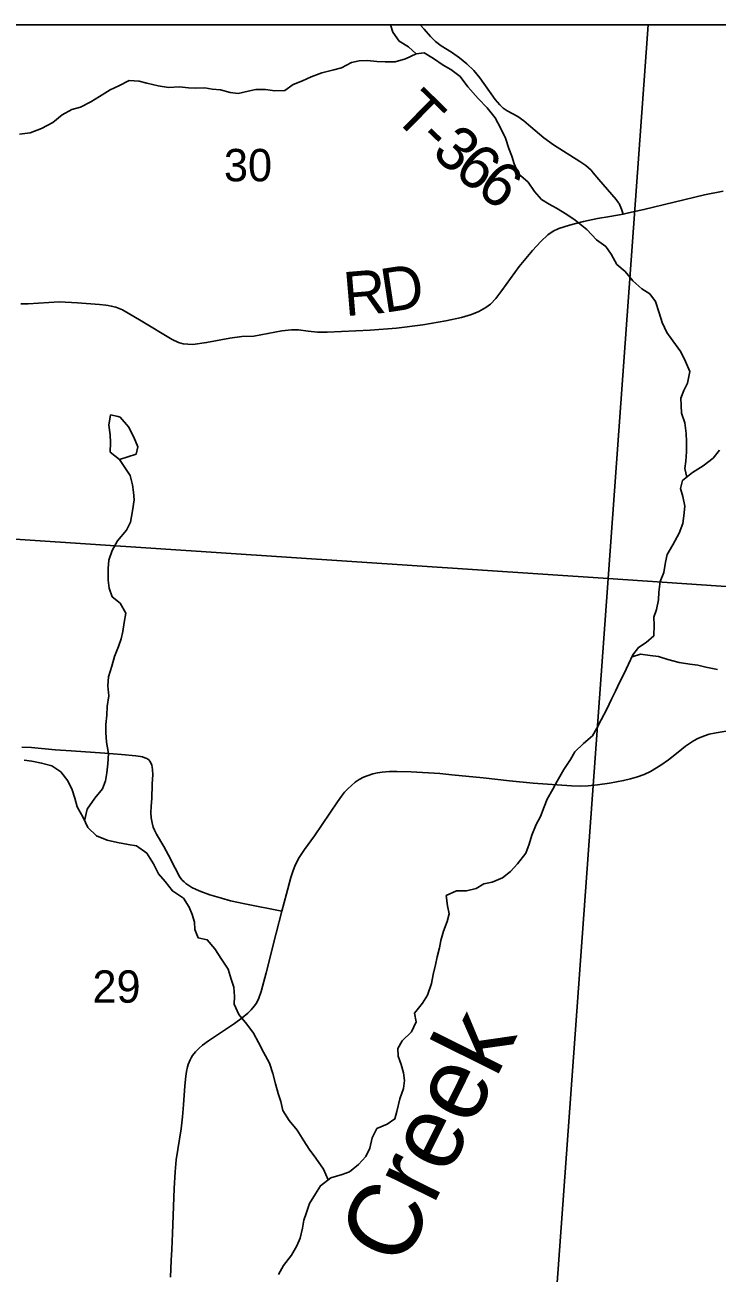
# Model space of a CAD drawing. Extents: x 39.8 to 73.8, y 13 to 35.
# Drawn here: x 44.827 to 45.722, y 32.252 to 33.865 of the extents above; entities that cross this region are included whole.
import ezdxf

# ---------------------------------------------------------------- set-up
doc = ezdxf.new("R2010")
doc.units = 0
for name, color, linetype in [('GM_X_Corporation', 7, 'Continuous'), ('GM_X_County_Road', 7, 'Continuous'), ('GM_X_Minor_Lake', 7, 'Continuous'), ('GM_X_Minor_River', 7, 'Continuous'), ('GM_X_Minor_River_Text', 7, 'Continuous'), ('GM_X_Section_Text', 7, 'Continuous'), ('GM_X_Township_Road', 7, 'Continuous'), ('GM_X_Township_Road_Text', 7, 'Continuous'), ('SH_Data', 7, 'Continuous')]:
    doc.layers.add(name, color=color, linetype=linetype)

msp = doc.modelspace()

# ---------------------------------------------------------------- linework, layer by layer
at = {"layer": 'GM_X_Corporation'}
msp.add_lwpolyline([(48.663, 33.865), (43.6158, 33.865), (43.5817, 33.4098), (43.5681, 33.1854), (43.5465, 32.861), (43.546, 32.8532), (43.5449, 32.8368), (43.542, 32.7932), (43.5417, 32.788), (43.5004, 32.1696), (43.4879, 31.9992), (43.4604, 31.6234), (43.4594, 31.6102), (43.4278, 31.1804), (43.4119, 30.9413), (43.3611, 30.1764), (43.3611, 30.1536), (43.3561, 30.0855), (43.3525, 30.036), (43.3481, 29.9766)], dxfattribs=at)
for points in [[(45.6327, 33.865), (44.6253, 33.865), (44.5795, 33.2157), (45.5809, 33.1493)], [(46.6307, 33.865), (45.6327, 33.865), (45.5809, 33.1493), (46.5718, 33.0824)], [(45.5809, 33.1493), (45.5069, 32.1262), (44.516, 32.1957), (44.5795, 33.2157)], [(45.5809, 33.1493), (46.5718, 33.0824), (46.4973, 32.0662), (45.5069, 32.1262)]]:
    msp.add_lwpolyline(points, close=True, dxfattribs=at)
at = {"layer": 'GM_X_County_Road'}
for points in [[(45.015, 32.2464), (45.016, 32.2681), (45.0165, 32.2821), (45.0174, 32.303), (45.0198, 32.3612), (45.021, 32.3828), (45.0224, 32.3983), (45.0287, 32.4382), (45.0305, 32.4535), (45.0318, 32.469), (45.0334, 32.4938), (45.0346, 32.5062), (45.0355, 32.5124), (45.0369, 32.5185), (45.0378, 32.5215), (45.039, 32.5245), (45.0403, 32.5274), (45.0418, 32.5301), (45.0435, 32.5328), (45.0474, 32.5378), (45.0518, 32.5423), (45.0565, 32.5464), (45.0641, 32.5519), (45.0796, 32.5623), (45.0978, 32.5742), (45.1078, 32.5815), (45.115, 32.5875), (45.1193, 32.5919), (45.1233, 32.5966), (45.125, 32.599), (45.1266, 32.6016), (45.1291, 32.6071), (45.132, 32.6159), (45.1386, 32.6398), (45.1517, 32.6909), (45.1591, 32.7196), (45.1649, 32.7419), (45.1705, 32.7631), (45.1735, 32.772), (45.1759, 32.7778), (45.1784, 32.7834), (45.1814, 32.789), (45.1884, 32.7993), (45.201, 32.817), (45.2307, 32.8607), (45.2362, 32.8683), (45.2401, 32.8732), (45.2443, 32.8778), (45.2489, 32.8821), (45.2538, 32.8861), (45.259, 32.8896), (45.2646, 32.8926), (45.2704, 32.895), (45.2764, 32.8969), (45.2825, 32.8983), (45.2887, 32.8993), (45.298, 32.9), (45.3074, 32.9001), (45.326, 32.8997), (45.3633, 32.8974), (45.3787, 32.8959), (45.4194, 32.8918), (45.4531, 32.888), (45.4837, 32.8851), (45.5333, 32.8816), (45.5456, 32.8812), (45.5549, 32.8815), (45.5672, 32.8827), (45.5825, 32.885), (45.6008, 32.8883), (45.6099, 32.8904), (45.6187, 32.893), (45.6274, 32.8962), (45.6358, 32.9001), (45.6489, 32.9081), (45.659, 32.9153), (45.6712, 32.925), (45.6809, 32.9327), (45.686, 32.9364), (45.6913, 32.9397), (45.6968, 32.9427), (45.6997, 32.944), (45.7055, 32.9463), (45.7115, 32.9481), (45.7207, 32.9501), (45.7361, 32.9525)], [(44.8227, 32.9317), (44.8351, 32.931), (44.8658, 32.9282), (44.8866, 32.9268), (44.9298, 32.9236), (44.9515, 32.9221), (44.97, 32.9205), (44.976, 32.9196), (44.9789, 32.9189), (44.9817, 32.9179), (44.9844, 32.9167), (44.9867, 32.915), (44.9881, 32.9133), (44.9895, 32.9111), (44.9906, 32.9083), (44.9912, 32.9055), (44.9916, 32.9022), (44.9919, 32.8962), (44.9914, 32.8838), (44.9906, 32.865), (44.9898, 32.8552), (44.9895, 32.8465), (44.99, 32.8402), (44.9911, 32.8339), (44.9927, 32.8283), (44.9943, 32.8243), (44.9968, 32.8192), (45.0063, 32.8031), (45.0124, 32.7919), (45.0208, 32.7752), (45.0265, 32.7643), (45.0282, 32.7618), (45.0301, 32.7596), (45.0324, 32.7574), (45.0348, 32.7553), (45.0374, 32.7535), (45.0427, 32.7502), (45.0483, 32.7474), (45.0541, 32.745), (45.0658, 32.7408), (45.0807, 32.7362), (45.0927, 32.7329), (45.1109, 32.7292), (45.1591, 32.7196)]]:
    msp.add_lwpolyline(points, dxfattribs=at)
at = {"layer": 'GM_X_Minor_Lake'}
for p, q in [((44.9372, 33.3611), (44.9353, 33.3478)), ((44.9471, 33.3587), (44.9372, 33.3611)), ((44.9353, 33.3478), (44.9369, 33.3353)), ((44.9497, 33.3581), (44.9471, 33.3587)), ((44.9607, 33.3456), (44.9497, 33.3581)), ((44.9676, 33.332), (44.9607, 33.3456)), ((44.9369, 33.3353), (44.9373, 33.3255)), ((44.9729, 33.3199), (44.9676, 33.332)), ((44.9373, 33.3255), (44.937, 33.3126)), ((44.937, 33.3126), (44.9488, 33.3035)), ((44.9707, 33.3104), (44.9729, 33.3199)), ((44.9488, 33.3035), (44.9707, 33.3104))]:
    msp.add_line(p, q, dxfattribs=at)
at = {"layer": 'GM_X_Minor_River'}
for p, q in [((45.3023, 33.8558), (45.2993, 33.865)), ((45.3107, 33.8441), (45.3023, 33.8558)), ((45.3225, 33.8365), (45.3107, 33.8441)), ((45.3328, 33.8278), (45.3225, 33.8365)), ((45.343, 33.829), (45.3328, 33.8278)), ((45.3551, 33.8215), (45.343, 33.829)), ((45.2491, 33.8166), (45.2359, 33.8097)), ((45.259, 33.8185), (45.2491, 33.8166)), ((45.2696, 33.8189), (45.259, 33.8185)), ((45.2817, 33.8178), (45.2696, 33.8189)), ((45.2923, 33.8175), (45.2817, 33.8178)), ((45.3055, 33.8175), (45.2923, 33.8175)), ((45.3188, 33.8213), (45.3055, 33.8175)), ((45.3328, 33.8278), (45.3188, 33.8213)), ((45.3677, 33.8128), (45.3551, 33.8215)), ((45.3775, 33.8075), (45.3677, 33.8128)), ((45.1969, 33.7978), (45.1856, 33.7928)), ((45.2106, 33.8032), (45.1969, 33.7978)), ((45.2261, 33.807), (45.2106, 33.8032)), ((45.2359, 33.8097), (45.2261, 33.807)), ((45.3897, 33.7984), (45.3775, 33.8075)), ((45.3996, 33.7848), (45.3897, 33.7984)), ((44.9369, 33.7811), (44.9233, 33.7723)), ((44.9482, 33.7864), (44.9369, 33.7811)), ((44.9614, 33.7933), (44.9482, 33.7864)), ((44.9743, 33.7922), (44.9614, 33.7933)), ((44.9842, 33.7899), (44.9743, 33.7922)), ((44.999, 33.7862), (44.9842, 33.7899)), ((45.0122, 33.7843), (44.999, 33.7862)), ((45.0266, 33.7848), (45.0122, 33.7843)), ((45.038, 33.7837), (45.0266, 33.7848)), ((45.0478, 33.7833), (45.038, 33.7837)), ((45.0592, 33.7837), (45.0478, 33.7833)), ((45.069, 33.7822), (45.0592, 33.7837)), ((45.0796, 33.7811), (45.069, 33.7822)), ((45.0921, 33.7778), (45.0796, 33.7811)), ((45.1251, 33.7817), (45.1152, 33.7793)), ((45.1379, 33.7817), (45.1251, 33.7817)), ((45.1497, 33.7798), (45.1379, 33.7817)), ((45.1629, 33.7803), (45.1497, 33.7798)), ((45.1735, 33.7879), (45.1629, 33.7803)), ((45.1856, 33.7928), (45.1735, 33.7879)), ((45.4129, 33.77), (45.3996, 33.7848)), ((44.912, 33.7658), (44.8984, 33.7586)), ((44.9233, 33.7723), (44.912, 33.7658)), ((45.1024, 33.7763), (45.0921, 33.7778)), ((45.1152, 33.7793), (45.1024, 33.7763)), ((45.4243, 33.7579), (45.4129, 33.77)), ((44.8749, 33.749), (44.8628, 33.7391)), ((44.8874, 33.7555), (44.8749, 33.749)), ((44.8984, 33.7586), (44.8874, 33.7555)), ((45.4346, 33.7451), (45.4243, 33.7579)), ((44.8628, 33.7391), (44.8481, 33.7311)), ((45.4418, 33.7318), (45.4346, 33.7451)), ((45.448, 33.7186), (45.4418, 33.7318)), ((44.8334, 33.7254), (44.8197, 33.7238)), ((44.8481, 33.7311), (44.8334, 33.7254)), ((45.4526, 33.7053), (45.448, 33.7186)), ((45.4564, 33.6955), (45.4526, 33.7053)), ((45.4591, 33.6856), (45.4564, 33.6955)), ((45.4648, 33.6727), (45.4591, 33.6856)), ((45.4774, 33.6618), (45.4648, 33.6727)), ((45.4854, 33.6496), (45.4774, 33.6618)), ((45.4945, 33.6394), (45.4854, 33.6496)), ((45.5047, 33.6334), (45.4945, 33.6394)), ((45.5142, 33.6281), (45.5047, 33.6334)), ((45.5275, 33.6202), (45.5142, 33.6281)), ((45.5382, 33.6126), (45.5275, 33.6202)), ((45.5534, 33.6005), (45.5382, 33.6126)), ((45.5659, 33.5873), (45.5534, 33.6005)), ((45.5777, 33.5786), (45.5659, 33.5873)), ((45.5849, 33.5688), (45.5777, 33.5786)), ((45.5922, 33.5555), (45.5849, 33.5688)), ((45.6028, 33.5465), (45.5922, 33.5555)), ((45.6127, 33.5343), (45.6028, 33.5465)), ((45.6245, 33.5238), (45.6127, 33.5343)), ((45.6347, 33.5173), (45.6245, 33.5238)), ((45.642, 33.5075), (45.6347, 33.5173)), ((45.6466, 33.4927), (45.642, 33.5075)), ((45.6508, 33.4802), (45.6466, 33.4927)), ((45.6569, 33.4673), (45.6508, 33.4802)), ((45.6645, 33.4567), (45.6569, 33.4673)), ((45.6748, 33.4427), (45.6645, 33.4567)), ((45.6809, 33.4299), (45.6748, 33.4427)), ((45.6863, 33.417), (45.6809, 33.4299)), ((45.6833, 33.4018), (45.6863, 33.417)), ((45.6788, 33.3923), (45.6833, 33.4018)), ((45.6747, 33.3828), (45.6788, 33.3923)), ((45.6751, 33.3733), (45.6747, 33.3828)), ((45.6759, 33.3631), (45.6751, 33.3733)), ((45.6801, 33.3506), (45.6759, 33.3631)), ((45.6817, 33.3369), (45.6801, 33.3506)), ((45.6821, 33.3267), (45.6817, 33.3369)), ((45.6811, 33.3013), (45.6822, 33.3134)), ((45.6822, 33.3134), (45.6821, 33.3267)), ((44.9629, 33.2827), (44.9488, 33.3035)), ((45.68, 33.2918), (45.6811, 33.3013)), ((44.9656, 33.2706), (44.9629, 33.2827)), ((45.6826, 33.2806), (45.68, 33.2918)), ((44.9671, 33.2611), (44.9656, 33.2706)), ((44.9657, 33.2368), (44.9679, 33.2512)), ((44.9679, 33.2512), (44.9671, 33.2611)), ((44.9631, 33.2224), (44.9657, 33.2368)), ((44.9579, 33.2121), (44.9631, 33.2224)), ((44.9462, 33.1984), (44.9579, 33.2121)), ((44.935, 33.173), (44.9394, 33.1855)), ((44.9394, 33.1855), (44.9462, 33.1984)), ((44.9342, 33.1623), (44.935, 33.173)), ((44.9343, 33.1472), (44.9342, 33.1623)), ((44.9355, 33.1369), (44.9343, 33.1472)), ((44.9393, 33.1259), (44.9355, 33.1369)), ((44.95, 33.1176), (44.9393, 33.1259)), ((44.9572, 33.1048), (44.95, 33.1176)), ((44.955, 33.0926), (44.9572, 33.1048)), ((44.9535, 33.0812), (44.955, 33.0926)), ((44.9479, 33.0615), (44.9513, 33.0714)), ((44.9513, 33.0714), (44.9535, 33.0812)), ((44.9423, 33.0486), (44.9479, 33.0615)), ((44.9389, 33.0364), (44.9423, 33.0486)), ((44.9341, 33.0106), (44.9348, 33.0224)), ((44.9348, 33.0224), (44.9389, 33.0364)), ((44.9353, 32.9977), (44.9341, 33.0106)), ((44.9331, 32.984), (44.9353, 32.9977)), ((44.9324, 32.9727), (44.9331, 32.984)), ((44.9313, 32.9609), (44.9324, 32.9727)), ((44.9314, 32.9503), (44.9313, 32.9609)), ((44.9322, 32.9381), (44.9314, 32.9503)), ((44.9349, 32.9234), (44.9322, 32.9381)), ((44.9327, 32.8983), (44.9338, 32.9101)), ((44.9338, 32.9101), (44.9349, 32.9234)), ((44.9309, 32.8881), (44.9327, 32.8983)), ((44.917, 32.8656), (44.9268, 32.8778)), ((44.9268, 32.8778), (44.9309, 32.8881)), ((44.9072, 32.8512), (44.917, 32.8656)), ((44.9039, 32.8363), (44.9072, 32.8512))]:
    msp.add_line(p, q, dxfattribs=at)
for points in [[(45.6529, 33.1574), (45.6548, 33.1707), (45.657, 33.1806), (45.6645, 33.1931), (45.6728, 33.2079), (45.6773, 33.2204), (45.6788, 33.2303), (45.6802, 33.2432), (45.6775, 33.2557), (45.6744, 33.266), (45.6771, 33.2762), (45.6899, 33.2865), (45.7035, 33.2953), (45.7167, 33.3052), (45.725, 33.3154)], [(45.1547, 32.25), (45.1611, 32.2617), (45.1713, 32.2747), (45.1784, 32.2868), (45.1826, 32.2967), (45.1855, 32.31), (45.1874, 32.3202), (45.1908, 32.3301), (45.1945, 32.3415), (45.2024, 32.354), (45.2088, 32.3647), (45.2224, 32.375), (45.2367, 32.3792), (45.2466, 32.3826), (45.2579, 32.3922), (45.2677, 32.4024), (45.2726, 32.4134), (45.2759, 32.4267), (45.2819, 32.4385), (45.2952, 32.4442), (45.305, 32.4511), (45.3076, 32.4606), (45.3113, 32.4769), (45.3162, 32.4902), (45.3176, 32.5005), (45.3161, 32.5107), (45.313, 32.5213), (45.3092, 32.5323), (45.3091, 32.5422), (45.3144, 32.552), (45.3264, 32.5635), (45.3325, 32.5764), (45.3305, 32.5877), (45.3407, 32.6007), (45.3474, 32.6109), (45.3523, 32.6261), (45.3545, 32.6375), (45.3575, 32.65), (45.3597, 32.6603), (45.3627, 32.6721), (45.3646, 32.6816), (45.3679, 32.6937), (45.3728, 32.7062), (45.3754, 32.7161), (45.3731, 32.7263), (45.3715, 32.7396), (45.3847, 32.7457), (45.3976, 32.7458), (45.4101, 32.7488), (45.4203, 32.7549), (45.4309, 32.7569), (45.4441, 32.7626), (45.4547, 32.771), (45.4637, 32.7805), (45.4746, 32.7946), (45.4788, 32.8063), (45.4821, 32.8177), (45.4877, 32.8314), (45.4934, 32.842), (45.4982, 32.8542), (45.502, 32.8641), (45.5095, 32.8774), (45.5151, 32.8876), (45.5234, 32.9025), (45.5321, 32.9154), (45.5377, 32.9256), (45.549, 32.9363), (45.5607, 32.9462), (45.566, 32.9561), (45.5716, 32.9667), (45.5791, 32.9808), (45.5851, 32.9937), (45.5904, 33.0039), (45.5956, 33.0153), (45.6013, 33.026), (45.6073, 33.0389), (45.6129, 33.0507), (45.62, 33.0602), (45.6299, 33.067), (45.6397, 33.0754), (45.6404, 33.0891), (45.6399, 33.0997), (45.6433, 33.1096), (45.6459, 33.1221), (45.6462, 33.132), (45.6481, 33.1456), (45.6529, 33.1574)], [(45.6118, 33.0483), (45.6227, 33.0515), (45.6352, 33.05), (45.6458, 33.0485), (45.658, 33.0448), (45.6728, 33.041), (45.6864, 33.0388), (45.697, 33.0373), (45.7072, 33.035), (45.7224, 33.0317)], [(45.2186, 32.3721), (45.2129, 32.3859), (45.2029, 32.4003), (45.1942, 32.4121), (45.1873, 32.4227), (45.1786, 32.4363), (45.1683, 32.4488), (45.1603, 32.462), (45.1576, 32.4734), (45.1541, 32.484), (45.1507, 32.4965), (45.1472, 32.5098), (45.143, 32.523), (45.1353, 32.5371), (45.1288, 32.5499), (45.1224, 32.5617), (45.1136, 32.5734), (45.1033, 32.5859), (45.0972, 32.5995), (45.0975, 32.6094), (45.0967, 32.6211), (45.0933, 32.6318), (45.0894, 32.6446), (45.0807, 32.6575), (45.0723, 32.6708), (45.0624, 32.6825), (45.0506, 32.6851), (45.0464, 32.6957), (45.046, 32.7052), (45.0429, 32.7151), (45.0391, 32.7245), (45.0319, 32.7363), (45.0174, 32.7457), (45.0079, 32.7578), (44.9995, 32.7677), (44.9931, 32.7805), (44.9843, 32.7945), (44.971, 32.804), (44.96, 32.8058), (44.9464, 32.8081), (44.9331, 32.8111), (44.9194, 32.8171), (44.908, 32.8277), (44.9019, 32.8406), (44.8943, 32.8542), (44.8912, 32.8656), (44.8878, 32.8762), (44.882, 32.8879), (44.8733, 32.8996), (44.8615, 32.9072), (44.8482, 32.9109), (44.8357, 32.9132), (44.8255, 32.9147)]]:
    msp.add_lwpolyline(points, dxfattribs=at)
at = {"layer": 'GM_X_Township_Road'}
for points in [[(45.6001, 33.6206), (45.598, 33.6269), (45.5949, 33.634), (45.5944, 33.635), (45.5914, 33.6395), (45.5689, 33.6653), (45.5615, 33.674), (45.5589, 33.6771), (45.552, 33.6833), (45.5444, 33.6887), (45.5101, 33.7099), (45.4976, 33.719), (45.481, 33.7331), (45.4716, 33.7412), (45.464, 33.7465), (45.4504, 33.754), (45.4453, 33.7575), (45.4407, 33.7617), (45.4348, 33.7688), (45.4149, 33.7966), (45.407, 33.8061), (45.3981, 33.8148), (45.3886, 33.8227), (45.3784, 33.8298), (45.3651, 33.8379), (45.3578, 33.8436), (45.3513, 33.8502), (45.343, 33.8594), (45.3379, 33.865)], [(44.9343, 33.5023), (44.9384, 33.5017), (44.9444, 33.5002), (44.953, 33.4966), (44.9771, 33.4825), (45.0169, 33.4586), (45.0253, 33.4547), (45.0313, 33.453), (45.0374, 33.4522), (45.0437, 33.4521), (45.0615, 33.4544), (45.0918, 33.4603), (45.1072, 33.4621), (45.1226, 33.4629), (45.1408, 33.4661), (45.159, 33.4697), (45.1713, 33.4711), (45.1805, 33.4709), (45.1928, 33.4693), (45.2049, 33.4678), (45.2176, 33.4677), (45.2733, 33.4706), (45.307, 33.473), (45.3411, 33.4772), (45.3708, 33.4825), (45.3912, 33.4869), (45.4041, 33.4907), (45.4135, 33.4945), (45.4228, 33.4998), (45.4287, 33.5042), (45.4354, 33.5113), (45.4434, 33.5219), (45.4656, 33.5526), (45.4831, 33.5736), (45.4937, 33.5849), (45.5028, 33.5935), (45.5096, 33.5983), (45.5171, 33.6017), (45.5308, 33.6061), (45.549, 33.6111), (45.5672, 33.615), (45.5831, 33.6175), (45.6001, 33.6206), (45.6073, 33.622), (45.6271, 33.6263), (45.7054, 33.6453), (45.7296, 33.6503)], [(44.8216, 33.5046), (44.8308, 33.5045), (44.8709, 33.5069), (44.8945, 33.5057), (44.923, 33.5037), (44.9311, 33.5027), (44.9343, 33.5023)]]:
    msp.add_lwpolyline(points, dxfattribs=at)
at = {"layer": 'SH_Data'}
msp.add_line((41.863, 33.865), (48.663, 33.865), dxfattribs=at)

# ---------------------------------------------------------------- texts
at = {"layer": 'GM_X_Minor_River_Text'}
msp.add_text('Creek', height=0.0947, rotation=63.6431, dxfattribs=at).set_placement((45.3139, 32.2563))
at = {"layer": 'GM_X_Section_Text'}
for s, p in [('30', (45.084, 33.6629)), ('29', (44.914, 32.6012))]:
    msp.add_text(s, height=0.04186, rotation=0, dxfattribs=at).set_placement(p)
at = {"layer": 'GM_X_Township_Road_Text'}
for s, rotation, p in [('T', 315.4758, (45.3014, 33.746)), ('3', 318.4686, (45.351, 33.6979)), ('-', 316.3527, (45.3324, 33.7155)), ('6', 320.9626, (45.3793, 33.6729)), ('6', 322.9668, (45.4081, 33.6495)), ('D', 8.692, (45.2914, 33.4928)), ('R', 4.787, (45.2408, 33.4885))]:
    msp.add_text(s, height=0.0568, rotation=rotation, dxfattribs=at).set_placement(p)

doc.saveas('drawing.dxf')
